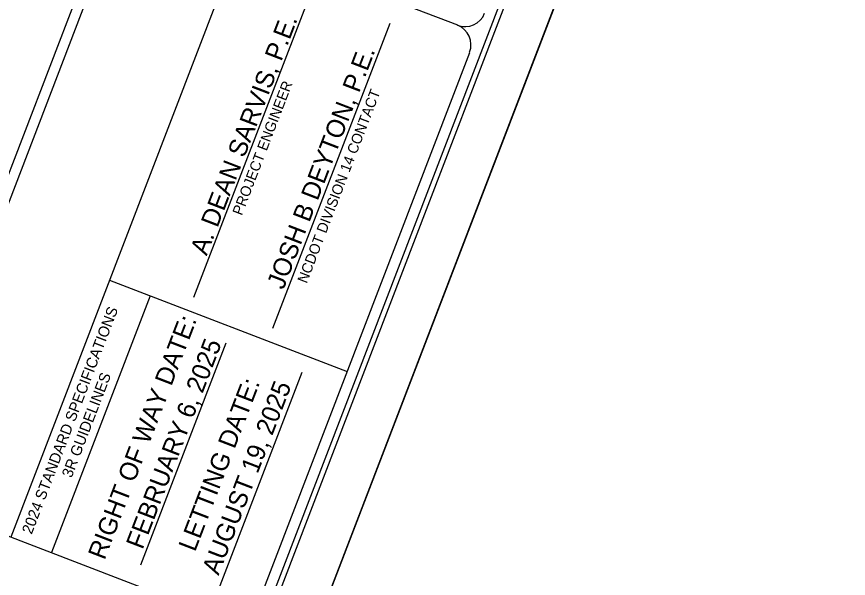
# Model space of a CAD drawing. Extents: x 1015221 to 1064345, y 619216 to 647967.
# Drawn here: x 1025084 to 1028267, y 639697 to 641845 of the extents above; entities that cross this region are included whole.
import ezdxf

# ---------------------------------------------------------------- set-up
doc = ezdxf.new("R2010")
doc.units = 0
for name, color, linetype in [('Sheet Cutting Line CELL', 7, 'Continuous'), ('Sheet Data Field CELL', 7, 'Continuous'), ('Sheet Plot Border Inside CELL', 7, 'Continuous'), ('Sheet Plot Border Outside CELL', 7, 'Continuous'), ('Sheet Title CELL', 7, 'Continuous')]:
    doc.layers.add(name, color=color, linetype=linetype)

msp = doc.modelspace()

# ---------------------------------------------------------------- linework, layer by layer
at = {"layer": 'Sheet Cutting Line CELL'}
msp.add_line((1023435, 632235.3), (1028266.7, 644811.1), dxfattribs=at)
at = {"layer": 'Sheet Plot Border Inside CELL'}
msp.add_lwpolyline([(1023304.8, 632396.8), (1028086.2, 644841.8), (1020206.9, 647869.1), (1015425.5, 635424)], close=True, dxfattribs=at)
at = {"layer": 'Sheet Plot Border Outside CELL'}
msp.add_lwpolyline([(1020052.2, 647967.1), (1015220.5, 635391.3), (1023435, 632235.3), (1028266.7, 644811.1)], close=True, dxfattribs=at)
at = {"layer": 'Sheet Title CELL'}
for p, q in [((1022495.1, 634584.7), (1026569.3, 645189)), ((1026771.6, 641811.7), (1025576.3, 642271)), ((1024655.2, 640096.6), (1025473, 642224.9)), ((1025937, 642132.4), (1025061.8, 639854.7)), ((1025762.2, 640772.2), (1026207.4, 641930.8)), ((1026064.3, 640653.1), (1026512.6, 641820)), ((1025439.3, 640837.1), (1026348.5, 640487.8)), ((1025594.2, 640777.6), (1025216.7, 639795.3)), ((1025884.3, 640596.4), (1025557.9, 639746.9)), ((1025399.7, 640527.5), (1025399.7, 640527.5)), ((1026175.5, 640484.5), (1025849.1, 639635)), ((1024701.2, 639993.3), (1025896.4, 639534.1))]:
    msp.add_line(p, q, dxfattribs=at)
for points in [[(1023756.2, 633628.8), (1028002.6, 644681.1)], [(1025999.8, 639580.1), (1026817.6, 641708.4)]]:
    msp.add_lwpolyline(points, dxfattribs=at)
for centre, start, end in [((1026799.9, 641886.6), 248.983, 338.983), ((1026742.5, 641737.2), 338.983, 68.983)]:
    msp.add_arc(centre, 80, start, end, dxfattribs=at)

# ---------------------------------------------------------------- texts
at = {"layer": 'Sheet Data Field CELL'}
for s, p in [('A. DEAN SARVIS, P.E.', (1025811, 640928)), ('JOSH B DEYTON, P.E.', (1026104.7, 640797.8)), ('FEBRUARY 6, 2025', (1025565.4, 639804)), ('AUGUST 19, 2025', (1025856.4, 639705.6))]:
    msp.add_text(s, height=70.001, rotation=68.983, dxfattribs=at).set_placement(p)
at = {"layer": 'Sheet Title CELL'}
for s, height, p in [('PROJECT ENGINEER', 39.996, (1025945.4, 641081.9)), ('NCDOT DIVISION 14 CONTACT', 39.996, (1026194, 640822.2)), ('2024 STANDARD SPECIFICATIONS', 41.6, (1025141.2, 639862.7)), ('RIGHT OF WAY DATE:', 69.998, (1025420, 639763.9)), ('3R GUIDELINES', 41.6, (1025293.9, 640078.4)), ('LETTING DATE:', 69.998, (1025766.3, 639795.4))]:
    msp.add_text(s, height=height, rotation=68.983, dxfattribs=at).set_placement(p)

doc.saveas('drawing.dxf')
